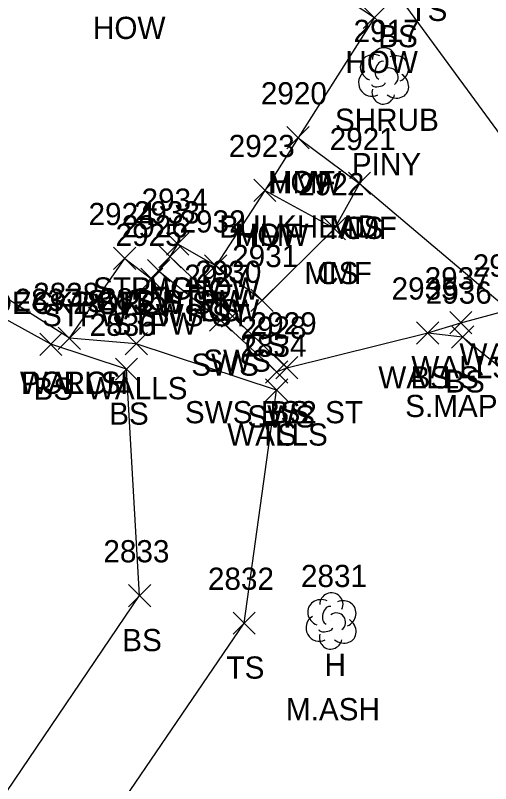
# Model space of a CAD drawing. Extents: x 1499292 to 1501024, y 534584 to 538043.
# Drawn here: x 1499706.6 to 1499749.5, y 537664.7 to 537733.8 of the extents above; entities that cross this region are included whole.
import ezdxf

# ---------------------------------------------------------------- set-up
doc = ezdxf.new("R2010")
doc.units = 0
for name, color, linetype in [('L_A', 7, 'Continuous'), ('L_C', 7, 'Continuous'), ('L_I', 7, 'Continuous'), ('L_TIC', 7, 'Continuous'), ('LBC', 7, 'Continuous'), ('LBF', 7, 'Continuous'), ('LDEFAULT', 7, 'Continuous'), ('LELB', 7, 'Continuous'), ('LSH', 7, 'Continuous'), ('LTD', 7, 'Continuous'), ('LWS', 7, 'Continuous'), ('R_A', 7, 'Continuous'), ('R_I', 7, 'Continuous'), ('R_TIC', 7, 'Continuous'), ('RSW', 7, 'Continuous')]:
    doc.layers.add(name, color=color, linetype=linetype)

msp = doc.modelspace()

# ---------------------------------------------------------------- linework, layer by layer
at = {"layer": 'L_TIC'}
for points in [[(1499737.986, 537732.643), (1499739.986, 537734.643)], [(1499739.986, 537732.643), (1499737.986, 537734.643)], [(1499731.104, 537721.822), (1499733.104, 537723.822)], [(1499733.104, 537721.822), (1499731.104, 537723.822)], [(1499731.104, 537721.822), (1499733.104, 537723.822)], [(1499733.104, 537721.822), (1499731.104, 537723.822)], [(1499736.647, 537717.705), (1499738.647, 537719.705)], [(1499738.647, 537717.705), (1499736.647, 537719.705)], [(1499736.647, 537717.705), (1499738.647, 537719.705)], [(1499738.647, 537717.705), (1499736.647, 537719.705)], [(1499728.121, 537717.079), (1499730.121, 537719.079)], [(1499730.121, 537717.079), (1499728.121, 537719.079)], [(1499728.121, 537717.079), (1499730.121, 537719.079)], [(1499730.121, 537717.079), (1499728.121, 537719.079)], [(1499734.388, 537713.637), (1499736.388, 537715.637)], [(1499736.388, 537713.637), (1499734.388, 537715.637)], [(1499734.388, 537713.637), (1499736.388, 537715.637)], [(1499736.388, 537713.637), (1499734.388, 537715.637)], [(1499720.272, 537712.245), (1499722.272, 537714.245)], [(1499722.272, 537712.245), (1499720.272, 537714.245)], [(1499720.272, 537712.245), (1499722.272, 537714.245)], [(1499722.272, 537712.245), (1499720.272, 537714.245)], [(1499715.497, 537710.951), (1499717.497, 537712.951)], [(1499717.497, 537710.951), (1499715.497, 537712.951)], [(1499715.497, 537710.951), (1499717.497, 537712.951)], [(1499717.497, 537710.951), (1499715.497, 537712.951)], [(1499719.58, 537711.102), (1499721.58, 537713.102)], [(1499721.58, 537711.102), (1499719.58, 537713.102)], [(1499718.553, 537709.842), (1499720.553, 537711.842)], [(1499720.553, 537709.842), (1499718.553, 537711.842)], [(1499723.689, 537710.282), (1499725.689, 537712.282)], [(1499725.689, 537710.282), (1499723.689, 537712.282)], [(1499723.689, 537710.282), (1499725.689, 537712.282)], [(1499725.689, 537710.282), (1499723.689, 537712.282)], [(1499717.936, 537709.078), (1499719.936, 537711.078)], [(1499719.936, 537709.078), (1499717.936, 537711.078)], [(1499727.866, 537707.17), (1499729.866, 537709.17)], [(1499729.866, 537707.17), (1499727.866, 537709.17)], [(1499745.766, 537705.161), (1499747.766, 537707.161)], [(1499747.766, 537705.161), (1499745.766, 537707.161)], [(1499710.512, 537703.758), (1499712.512, 537705.758)], [(1499712.512, 537703.758), (1499710.512, 537705.758)], [(1499710.512, 537703.758), (1499712.512, 537705.758)], [(1499712.512, 537703.758), (1499710.512, 537705.758)], [(1499710.512, 537703.758), (1499712.512, 537705.758)], [(1499712.512, 537703.758), (1499710.512, 537705.758)], [(1499742.79, 537704.244), (1499744.79, 537706.244)], [(1499744.79, 537704.244), (1499742.79, 537706.244)], [(1499742.79, 537704.244), (1499744.79, 537706.244)], [(1499744.79, 537704.244), (1499742.79, 537706.244)], [(1499745.925, 537703.877), (1499747.925, 537705.877)], [(1499747.925, 537703.877), (1499745.925, 537705.877)], [(1499708.841, 537703.22), (1499710.841, 537705.22)], [(1499710.841, 537703.22), (1499708.841, 537705.22)], [(1499716.542, 537703.267), (1499718.542, 537705.267)], [(1499718.542, 537703.267), (1499716.542, 537705.267)], [(1499715.653, 537700.977), (1499717.653, 537702.977)], [(1499717.653, 537700.977), (1499715.653, 537702.977)], [(1499730.101, 537701.105), (1499732.101, 537703.105)], [(1499732.101, 537701.105), (1499730.101, 537703.105)], [(1499729.18, 537699.095), (1499731.18, 537701.095)], [(1499731.18, 537699.095), (1499729.18, 537701.095)], [(1499729.18, 537699.095), (1499731.18, 537701.095)], [(1499731.18, 537699.095), (1499729.18, 537701.095)], [(1499716.834, 537680.585), (1499718.834, 537682.585)], [(1499718.834, 537680.585), (1499716.834, 537682.585)], [(1499726.251, 537678.109), (1499728.251, 537680.109)], [(1499728.251, 537678.109), (1499726.251, 537680.109)]]:
    msp.add_lwpolyline(points, dxfattribs=at)
at = {"layer": 'LBC'}
msp.add_lwpolyline([(1499697.587, 537727.89), (1499690.115, 537732.638), (1499693.073, 537737.884), (1499694.333, 537739.703), (1499698.305, 537745.626), (1499698.593, 537746.054), (1499699.211, 537747.217), (1499705.404, 537743.454), (1499710.54, 537740.083), (1499716.249, 537736.711), (1499721.755, 537744.999), (1499738.986, 537733.643), (1499732.104, 537722.822), (1499729.121, 537718.079), (1499724.689, 537711.282), (1499721.272, 537713.245)], dxfattribs=at)
at = {"layer": 'LBF'}
for points in [[(1499711.512, 537704.758), (1499700.017, 537712.028), (1499691.247, 537717.506), (1499690.99, 537717.994), (1499694.065, 537722.825), (1499696.32, 537726.361), (1499697.587, 537727.89)], [(1499716.497, 537711.951), (1499718.936, 537710.078), (1499719.553, 537710.842), (1499720.58, 537712.102), (1499721.272, 537713.245)], [(1499711.512, 537704.758), (1499716.497, 537711.951)]]:
    msp.add_lwpolyline(points, dxfattribs=at)
at = {"layer": 'LDEFAULT'}
msp.add_lwpolyline([(1499732.104, 537722.822), (1499737.647, 537718.705), (1499735.388, 537714.637), (1499729.121, 537718.079)], dxfattribs=at)
at = {"layer": 'LELB'}
for points in [[(1499673.505, 537786.342), (1499677.07, 537783.592), (1499700.821, 537763.481), (1499719.743, 537752.304), (1499723.657, 537747.33), (1499740.89, 537735.965), (1499752.712, 537719.821), (1499760.138, 537714.193), (1499776.543, 537702.52), (1499783.898, 537695.878)], [(1499737.647, 537718.705), (1499751.097, 537707.315), (1499759.552, 537703.258), (1499771.334, 537695.953)], [(1499703.218, 537660.051), (1499717.834, 537681.585), (1499716.653, 537701.977), (1499709.841, 537704.22), (1499697.889, 537710.799), (1499690.594, 537717.051), (1499690.99, 537717.994)], [(1499735.388, 537714.637), (1499728.866, 537708.17), (1499724.689, 537711.282)], [(1499731.101, 537702.105), (1499743.79, 537705.244), (1499746.925, 537704.877), (1499754.605, 537698.679), (1499771.599, 537687.444), (1499770.394, 537675.679), (1499771.532, 537669.102)], [(1499709.086, 537652.452), (1499727.251, 537679.109), (1499730.18, 537700.095)]]:
    msp.add_lwpolyline(points, dxfattribs=at)
at = {"layer": 'LSH'}
msp.add_line((1499739.799, 537728.439), (1499739.799, 537728.439), dxfattribs=at)
msp.add_line((1499739.799, 537728.439), (1499739.799, 537728.439), dxfattribs=at)
msp.add_arc((1499739.846, 537729.873), 1.047, 335.52715, 180.95627, dxfattribs=at)
for centre, major_axis, ratio, start_param, end_param in [((1499739.007, 537729.105), (1.21, -0.512), 0.895232, 1.570796, 4.712389), ((1499740.841, 537729.022), (-1.141, -0.483), 0.949671, 1.570796, 4.712389), ((1499739.591, 537728.897), (-0.208, -0.792), 0.645439, 3.141593, 6.283185), ((1499740.299, 537728.272), (-0.5, 0.667), 0.989748, 3.141593, 6.283185), ((1499738.716, 537727.73), (0.584, -1.042), 0.959034, 3.141593, 6.283185), ((1499740.799, 537727.605), (-1.09, 0.792), 0.841452, 1.570796, 4.712389), ((1499739.341, 537727.688), (-0.625, -0.083), 0.423636, 0, 3.141593), ((1499739.799, 537726.939), (0.265, 1.061), 0.942809, 1.570796, 4.712389)]:
    msp.add_ellipse(centre, major_axis=major_axis, ratio=ratio, start_param=start_param, end_param=end_param, dxfattribs=at)
at = {"layer": 'LTD'}
msp.add_line((1499735.063, 537679.361), (1499735.063, 537679.361), dxfattribs=at)
msp.add_line((1499735.063, 537679.361), (1499735.063, 537679.361), dxfattribs=at)
msp.add_arc((1499735.11, 537680.795), 1.047, 335.52715, 180.95627, dxfattribs=at)
for centre, major_axis, ratio, start_param, end_param in [((1499734.272, 537680.028), (1.21, -0.512), 0.895232, 1.570796, 4.712389), ((1499734.855, 537679.82), (-0.208, -0.792), 0.645439, 3.141593, 6.283185), ((1499736.105, 537679.945), (-1.141, -0.483), 0.949671, 1.570796, 4.712389), ((1499735.563, 537679.195), (-0.5, 0.667), 0.989748, 3.141593, 6.283185), ((1499733.98, 537678.653), (0.584, -1.042), 0.959034, 3.141593, 6.283185), ((1499736.063, 537678.528), (-1.09, 0.792), 0.841452, 1.570796, 4.712389), ((1499734.605, 537678.611), (-0.625, -0.083), 0.423636, 0, 3.141593), ((1499735.064, 537677.861), (0.265, 1.061), 0.942809, 1.570796, 4.712389)]:
    msp.add_ellipse(centre, major_axis=major_axis, ratio=ratio, start_param=start_param, end_param=end_param, dxfattribs=at)
at = {"layer": 'LWS'}
for points in [[(1499730.18, 537700.095), (1499717.542, 537704.267), (1499711.512, 537704.758), (1499700.017, 537712.028), (1499691.247, 537717.506)], [(1499743.79, 537705.244), (1499746.766, 537706.161), (1499751.097, 537707.315)]]:
    msp.add_lwpolyline(points, dxfattribs=at)
at = {"layer": 'R_TIC'}
for points in [[(1499719.58, 537711.102), (1499721.58, 537713.102)], [(1499721.58, 537711.102), (1499719.58, 537713.102)], [(1499718.553, 537709.842), (1499720.553, 537711.842)], [(1499720.553, 537709.842), (1499718.553, 537711.842)], [(1499725.203, 537705.748), (1499727.203, 537707.748)], [(1499727.203, 537705.748), (1499725.203, 537707.748)], [(1499724.12, 537705.389), (1499726.12, 537707.389)], [(1499726.12, 537705.389), (1499724.12, 537707.389)], [(1499730.101, 537701.105), (1499732.101, 537703.105)], [(1499732.101, 537701.105), (1499730.101, 537703.105)], [(1499729.177, 537700.725), (1499731.177, 537702.725)], [(1499731.177, 537700.725), (1499729.177, 537702.725)]]:
    msp.add_lwpolyline(points, dxfattribs=at)
at = {"layer": 'RSW'}
msp.add_lwpolyline([(1499719.553, 537710.842), (1499725.12, 537706.389), (1499730.177, 537701.725), (1499731.101, 537702.105), (1499726.203, 537706.748), (1499720.58, 537712.102)], dxfattribs=at)

# ---------------------------------------------------------------- texts
at = {"layer": 'L_A'}
for s, p in [('TS', (1499742.138, 537733.33)), ('HOW', (1499713.634, 537731.711)), ('BS', (1499739.331, 537730.965)), ('HOW', (1499736.371, 537728.643)), ('SHRUB', (1499735.429, 537723.439)), ('MMF', (1499729.387, 537717.822)), ('HOW', (1499729.489, 537717.822)), ('MMF', (1499734.931, 537713.705)), ('CS', (1499736.088, 537713.705)), ('MMF', (1499726.404, 537713.079)), ('HOW', (1499726.507, 537713.079)), ('MMF', (1499732.671, 537709.637)), ('CS', (1499733.829, 537709.637)), ('STPW HOW', (1499713.65, 537708.245)), ('HOW', (1499718.657, 537708.245)), ('SWS STPW', (1499713.069, 537707.102)), ('DECK2 STPW ST', (1499704.411, 537706.951)), ('PORCH', (1499712.119, 537706.951)), ('STPW SWS ST', (1499709.042, 537705.842)), ('HOW', (1499722.075, 537706.282)), ('CS', (1499723.13, 537706.282)), ('STPW', (1499715.329, 537705.078)), ('CS', (1499727.307, 537703.17)), ('WALLS', (1499746.641, 537702.315)), ('WALLS', (1499742.31, 537701.161)), ('WALLS', (1499739.334, 537700.244)), ('BS', (1499742.231, 537700.244)), ('WALLS', (1499707.056, 537699.758)), ('PORCH', (1499707.134, 537699.758)), ('PORCH', (1499707.134, 537699.758)), ('BS', (1499745.366, 537699.877)), ('BS', (1499708.282, 537699.22)), ('WALLS', (1499713.085, 537699.267)), ('BS', (1499715.094, 537696.977)), ('BS', (1499729.542, 537697.105)), ('WALLS', (1499725.723, 537695.095)), ('TS', (1499728.589, 537695.095)), ('BS', (1499716.275, 537676.585)), ('TS', (1499725.66, 537674.109)), ('H', (1499734.496, 537674.361))]:
    msp.add_text(s, height=2, dxfattribs=at).set_placement(p)
at = {"layer": 'L_C'}
for s, p in [('PINY', (1499736.949, 537719.439)), ('BULKHEAD', (1499725.009, 537713.822)), ('S.MAPLE LILAC', (1499741.755, 537697.666)), ('M.ASH', (1499731.016, 537670.361))]:
    msp.add_text(s, height=2, dxfattribs=at).set_placement(p)
at = {"layer": 'L_I'}
for s, p in [('2917', (1499737.106, 537731.439)), ('2920', (1499728.757, 537725.822)), ('2920', (1499728.757, 537725.822)), ('2921', (1499734.954, 537721.705)), ('2921', (1499734.954, 537721.705)), ('2923', (1499725.861, 537721.079)), ('2923', (1499725.861, 537721.079)), ('2922', (1499732.128, 537717.637)), ('2922', (1499732.128, 537717.637)), ('2934', (1499718.012, 537716.245)), ('2934', (1499718.012, 537716.245)), ('2924', (1499713.237, 537714.951)), ('2924', (1499713.237, 537714.951)), ('2933', (1499717.321, 537715.102)), ('2932', (1499721.429, 537714.282)), ('2932', (1499721.429, 537714.282)), ('2926', (1499716.238, 537713.842)), ('2925', (1499715.676, 537713.078)), ('2931', (1499726.173, 537711.17)), ('2938', (1499747.838, 537710.315)), ('2938', (1499747.838, 537710.315)), ('2937', (1499743.507, 537709.161)), ('2838', (1499708.252, 537707.758)), ('2838', (1499708.252, 537707.758)), ('2838', (1499708.252, 537707.758)), ('2935', (1499740.531, 537708.244)), ('2935', (1499740.531, 537708.244)), ('2936', (1499743.61, 537707.877)), ('2837', (1499706.582, 537707.22)), ('2835', (1499714.282, 537707.267)), ('2836', (1499713.338, 537704.977)), ('2929', (1499727.833, 537705.105)), ('2834', (1499726.92, 537703.095)), ('2834', (1499726.92, 537703.095)), ('2833', (1499714.574, 537684.585)), ('2832', (1499723.991, 537682.109)), ('2831', (1499732.37, 537682.361))]:
    msp.add_text(s, height=2, dxfattribs=at).set_placement(p)
at = {"layer": 'R_A'}
for s, p in [('SWS STPW', (1499713.069, 537707.102)), ('STPW SWS ST', (1499709.042, 537705.842)), ('SWS', (1499723.573, 537701.748)), ('SWS', (1499722.49, 537701.389)), ('SWS BS2 ST', (1499721.912, 537697.105)), ('SWS', (1499727.547, 537696.725))]:
    msp.add_text(s, height=2, dxfattribs=at).set_placement(p)
at = {"layer": 'R_I'}
for s, p in [('2933', (1499717.321, 537715.102)), ('2926', (1499716.238, 537713.842)), ('2927', (1499721.861, 537709.389)), ('2930', (1499722.857, 537709.748)), ('2929', (1499727.833, 537705.105)), ('2928', (1499726.917, 537704.725))]:
    msp.add_text(s, height=2, dxfattribs=at).set_placement(p)

doc.saveas('drawing.dxf')
